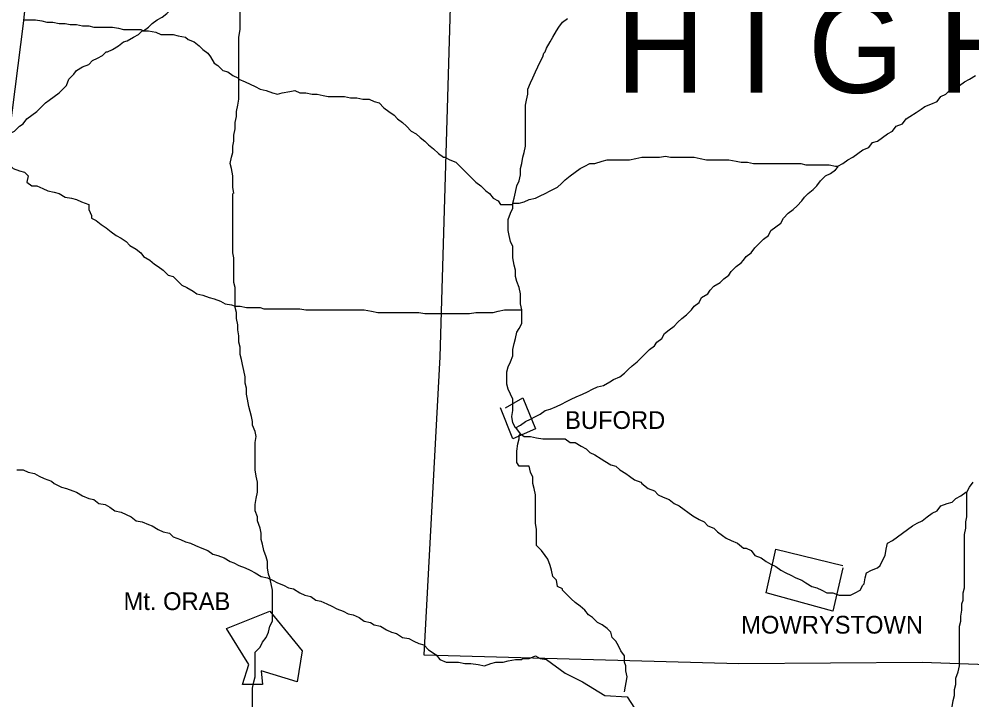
# Model space of a CAD drawing. Extents: x 0 to 34, y 0 to 22.
# Drawn here: x 2.531 to 3.578, y 17.75 to 18.498 of the extents above; entities that cross this region are included whole.
import ezdxf

# ---------------------------------------------------------------- set-up
doc = ezdxf.new("R2010")
doc.units = 0
doc.layers.add('Default', color=7, linetype='Continuous')
doc.layers.add('TR_Turning_Path1', color=7, linetype='Continuous')

msp = doc.modelspace()

# ---------------------------------------------------------------- linework, layer by layer
at = {"layer": 'Default'}
for points in [[(2.5636, 18.8615), (2.5554, 18.732), (2.5473, 18.6093), (2.535, 18.4934), (2.52, 18.3748), (2.5173, 18.3407), (2.5009, 18.2016), (2.4832, 18.0612), (2.4655, 17.914), (2.4109, 17.4668), (2.3877, 17.2759), (2.3646, 17.0891), (2.3209, 16.7073), (2.3168, 16.6787)], [(3.0135, 18.822), (2.9931, 18.1267), (2.9754, 17.7994), (3.3217, 17.7899), (3.5235, 17.7913), (3.6353, 17.7872), (3.6789, 17.7858)], [(2.6672, 18.4852), (2.6727, 18.4893), (2.6768, 18.4934), (2.6822, 18.4975), (2.6877, 18.5002), (2.6931, 18.5043), (2.6986, 18.5098), (2.7041, 18.5125), (2.7081, 18.5166), (2.7136, 18.5207), (2.719, 18.5234), (2.7245, 18.5275), (2.73, 18.5316), (2.7354, 18.5357), (2.7409, 18.5398), (2.745, 18.5439), (2.749, 18.5466), (2.7559, 18.548), (2.7627, 18.5493), (2.7695, 18.5507), (2.7722, 18.5507)], [(2.7722, 18.4321), (2.7722, 18.4402), (2.7722, 18.4457), (2.7722, 18.4539), (2.7722, 18.4593), (2.7722, 18.4662), (2.7722, 18.473), (2.7722, 18.4784), (2.7736, 18.4866), (2.7736, 18.4921), (2.7736, 18.4975), (2.7736, 18.5043), (2.7736, 18.5111), (2.7722, 18.5166), (2.7722, 18.5221), (2.7722, 18.5302), (2.7722, 18.5357), (2.7736, 18.5411), (2.7736, 18.548), (2.7722, 18.5507)], [(2.535, 18.4975), (2.5418, 18.4975), (2.5486, 18.4975), (2.5554, 18.4961), (2.5609, 18.4948), (2.5677, 18.4948), (2.5745, 18.4934), (2.5813, 18.4934), (2.5868, 18.4921), (2.5936, 18.4921), (2.6004, 18.4907), (2.6072, 18.4907), (2.6127, 18.4893), (2.6195, 18.4893), (2.6263, 18.4893), (2.6332, 18.4893), (2.64, 18.488), (2.6454, 18.4866), (2.6509, 18.4866), (2.6591, 18.4866), (2.6645, 18.4866), (2.6672, 18.4852)], [(3.109, 18.4621), (3.1104, 18.4662), (3.1144, 18.473), (3.1172, 18.4784), (3.1213, 18.4852), (3.124, 18.4893), (3.1281, 18.4948), (3.1335, 18.4989)], [(2.6277, 18.4621), (2.6332, 18.4648), (2.64, 18.4689), (2.6454, 18.473), (2.6495, 18.4743), (2.6563, 18.4784), (2.6618, 18.4811), (2.6659, 18.4852), (2.6672, 18.4852)], [(2.6672, 18.4852), (2.6727, 18.4852), (2.6809, 18.4839), (2.6863, 18.4811), (2.6918, 18.4811), (2.7, 18.4811), (2.7054, 18.4798), (2.7136, 18.4784), (2.7163, 18.4757), (2.7231, 18.473), (2.7286, 18.4689), (2.7327, 18.4648), (2.7381, 18.4607), (2.7409, 18.4566), (2.745, 18.4498), (2.749, 18.4471), (2.7545, 18.4416), (2.76, 18.4402), (2.7654, 18.4362), (2.7709, 18.4334), (2.7722, 18.4321)], [(2.52, 18.3721), (2.5254, 18.3748), (2.5309, 18.3803), (2.535, 18.383), (2.5391, 18.3884), (2.5445, 18.3925), (2.55, 18.3966), (2.5541, 18.4007), (2.5595, 18.4062), (2.5636, 18.4089), (2.5691, 18.413), (2.5745, 18.4171), (2.5786, 18.4212), (2.5827, 18.4252), (2.5854, 18.4321), (2.5909, 18.4375), (2.5936, 18.4416), (2.6004, 18.4457), (2.6072, 18.4484), (2.6113, 18.4525), (2.6168, 18.4552), (2.6222, 18.458), (2.6263, 18.4621), (2.6277, 18.4621)], [(3.0735, 18.2957), (3.0749, 18.3012), (3.0763, 18.308), (3.0776, 18.3148), (3.0804, 18.3203), (3.0817, 18.3271), (3.0817, 18.3339), (3.0831, 18.3394), (3.0844, 18.3462), (3.0858, 18.3516), (3.0872, 18.3584), (3.0872, 18.3639), (3.0872, 18.3707), (3.0872, 18.3775), (3.0872, 18.383), (3.0872, 18.3898), (3.0872, 18.3966), (3.0872, 18.4034), (3.0885, 18.4089), (3.0899, 18.4157), (3.0899, 18.4212), (3.0926, 18.428), (3.0954, 18.4334), (3.0981, 18.4402), (3.1008, 18.4457), (3.1035, 18.4512), (3.1063, 18.4566), (3.1076, 18.4607), (3.109, 18.4621)], [(2.7668, 18.3066), (2.7654, 18.3134), (2.7654, 18.3203), (2.7654, 18.3257), (2.764, 18.3339), (2.7627, 18.3394), (2.764, 18.3462), (2.7654, 18.3516), (2.7654, 18.3584), (2.7668, 18.3639), (2.7668, 18.3707), (2.7681, 18.3775), (2.7681, 18.3843), (2.7695, 18.3912), (2.7695, 18.3966), (2.7709, 18.4034), (2.7722, 18.4103), (2.7722, 18.4157), (2.7722, 18.4225), (2.7722, 18.4293), (2.7722, 18.4321)], [(2.7722, 18.4321), (2.779, 18.4293), (2.7845, 18.4266), (2.7899, 18.4239), (2.7954, 18.4212), (2.8022, 18.4198), (2.809, 18.4171), (2.8145, 18.4157), (2.8199, 18.4171), (2.8281, 18.4184), (2.8336, 18.4198), (2.839, 18.4171), (2.8458, 18.4171), (2.8527, 18.4157), (2.8581, 18.4157), (2.8649, 18.4143), (2.8704, 18.413), (2.8786, 18.413), (2.8827, 18.413), (2.8827, 18.413)], [(3.4308, 18.3366), (3.4362, 18.3394), (3.4417, 18.3434), (3.4471, 18.3462), (3.4526, 18.3503), (3.458, 18.3544), (3.4648, 18.3571), (3.4689, 18.3625), (3.4744, 18.3639), (3.4798, 18.368), (3.4853, 18.3721), (3.4907, 18.3748), (3.4948, 18.3803), (3.5017, 18.383), (3.5057, 18.3884), (3.5098, 18.3912), (3.5167, 18.3953), (3.5221, 18.3993), (3.5262, 18.4021), (3.533, 18.4048), (3.5398, 18.4075), (3.5439, 18.413), (3.5494, 18.4157), (3.5535, 18.4198), (3.5589, 18.4225), (3.5644, 18.4252), (3.5698, 18.4293), (3.5753, 18.4321), (3.5821, 18.4362)], [(2.8827, 18.413), (2.8881, 18.413), (2.8949, 18.4116), (2.9017, 18.4116), (2.9086, 18.4103), (2.9154, 18.4103), (2.9208, 18.4075), (2.9263, 18.4062), (2.9317, 18.4007), (2.9372, 18.3966), (2.9427, 18.3925), (2.9467, 18.3884), (2.9522, 18.3843), (2.9563, 18.3803), (2.9617, 18.3748), (2.9672, 18.3721), (2.9713, 18.368), (2.9767, 18.3639), (2.9808, 18.3598), (2.9863, 18.3557), (2.9917, 18.3503), (2.9972, 18.3462), (2.9986, 18.3462)], [(2.5173, 18.3475), (2.52, 18.3434), (2.52, 18.338), (2.5241, 18.3339), (2.5309, 18.3312), (2.5364, 18.3298), (2.5404, 18.3257), (2.5391, 18.3189), (2.5445, 18.3148), (2.55, 18.3148), (2.5568, 18.3121), (2.5623, 18.3094), (2.5691, 18.308), (2.5745, 18.3066), (2.5813, 18.3025), (2.5882, 18.3012), (2.5936, 18.2998), (2.5991, 18.2971), (2.6072, 18.2944), (2.6072, 18.2889), (2.61, 18.2821), (2.61, 18.2821), (2.61, 18.2794)], [(2.9986, 18.3462), (3.004, 18.3434), (3.0108, 18.3407), (3.0135, 18.338), (3.019, 18.3325), (3.0245, 18.3271), (3.0285, 18.323), (3.0326, 18.3189), (3.0381, 18.3148), (3.0435, 18.3094), (3.0476, 18.3066), (3.0517, 18.3012), (3.0572, 18.2985), (3.0599, 18.2944), (3.0667, 18.2944), (3.0735, 18.2944), (3.0735, 18.2957)], [(3.0735, 18.2957), (3.0804, 18.2957), (3.0858, 18.2971), (3.0913, 18.2998), (3.0981, 18.3012), (3.1035, 18.3039), (3.109, 18.3066), (3.1144, 18.3094), (3.1226, 18.3134), (3.1267, 18.3175), (3.1308, 18.3216), (3.1363, 18.3257), (3.1417, 18.3298), (3.1472, 18.3339), (3.1526, 18.3366), (3.1581, 18.3394), (3.1635, 18.3394), (3.1717, 18.3421), (3.1772, 18.3434), (3.1826, 18.3434), (3.1894, 18.3434), (3.1962, 18.3434), (3.2017, 18.3434), (3.2085, 18.3448), (3.2153, 18.3462), (3.2208, 18.3462), (3.2276, 18.3462), (3.229, 18.3462)], [(3.229, 18.3462), (3.2344, 18.3462), (3.2412, 18.3475), (3.2467, 18.3462), (3.2535, 18.3462), (3.2603, 18.3462), (3.2658, 18.3462), (3.2726, 18.3462), (3.2794, 18.3448), (3.2862, 18.3434), (3.293, 18.3434), (3.2985, 18.3434), (3.3053, 18.3434), (3.3108, 18.3434), (3.319, 18.3421), (3.3244, 18.3407), (3.3312, 18.3407), (3.338, 18.3394), (3.3449, 18.3394), (3.3517, 18.3394), (3.3571, 18.3394), (3.3626, 18.3394), (3.3708, 18.3394), (3.3762, 18.3394), (3.383, 18.3394), (3.3899, 18.3394), (3.3953, 18.338), (3.4035, 18.338), (3.4089, 18.338), (3.4171, 18.338), (3.4212, 18.338), (3.428, 18.3366), (3.4308, 18.3366)], [(3.3271, 18.233), (3.3299, 18.2371), (3.3353, 18.2412), (3.3394, 18.2466), (3.3449, 18.2521), (3.3489, 18.2562), (3.3544, 18.2603), (3.3571, 18.2657), (3.3626, 18.2698), (3.368, 18.2739), (3.3708, 18.2794), (3.3762, 18.2848), (3.3817, 18.2889), (3.3858, 18.293), (3.3912, 18.2985), (3.3939, 18.3025), (3.398, 18.3066), (3.4035, 18.3107), (3.4076, 18.3148), (3.4117, 18.3203), (3.4171, 18.3257), (3.4226, 18.3284), (3.428, 18.3325), (3.4308, 18.3353), (3.4308, 18.3366)], [(2.7681, 18.1826), (2.7681, 18.1894), (2.7681, 18.1962), (2.7681, 18.203), (2.7668, 18.2085), (2.7668, 18.2153), (2.7668, 18.2221), (2.7668, 18.2276), (2.7668, 18.2357), (2.7654, 18.2412), (2.7654, 18.2466), (2.7654, 18.2535), (2.7654, 18.2603), (2.7654, 18.2671), (2.7654, 18.2725), (2.7654, 18.2794), (2.7654, 18.2862), (2.7654, 18.293), (2.7654, 18.2998), (2.7654, 18.3066), (2.7654, 18.3066)], [(3.0831, 18.1785), (3.0817, 18.1853), (3.0817, 18.1921), (3.0817, 18.1962), (3.0804, 18.203), (3.0776, 18.2098), (3.0763, 18.2153), (3.0763, 18.2221), (3.0749, 18.2276), (3.0735, 18.2357), (3.0735, 18.2412), (3.0735, 18.248), (3.0708, 18.2535), (3.0694, 18.2603), (3.0681, 18.2657), (3.0681, 18.2725), (3.0681, 18.278), (3.0708, 18.2848), (3.0735, 18.2903), (3.0735, 18.2957)], [(2.61, 18.2794), (2.6154, 18.2766), (2.6209, 18.2725), (2.6263, 18.2685), (2.6318, 18.2644), (2.6372, 18.2603), (2.6427, 18.2575), (2.6482, 18.2535), (2.6522, 18.2494), (2.6591, 18.2453), (2.6645, 18.2412), (2.6672, 18.2371), (2.6741, 18.233), (2.6795, 18.2289), (2.6836, 18.2262), (2.6891, 18.2221), (2.6945, 18.2166), (2.7, 18.2153), (2.7054, 18.2098), (2.7095, 18.2057), (2.715, 18.203), (2.7218, 18.1989), (2.7259, 18.1962), (2.7327, 18.1948), (2.7395, 18.1921), (2.745, 18.1907), (2.7518, 18.188), (2.7572, 18.1853), (2.764, 18.1839), (2.7681, 18.1826), (2.7681, 18.1826)], [(3.2044, 18.1171), (3.2099, 18.1212), (3.214, 18.1253), (3.2181, 18.1294), (3.2235, 18.1348), (3.229, 18.1389), (3.2317, 18.143), (3.2371, 18.1471), (3.2399, 18.1526), (3.2453, 18.1567), (3.2508, 18.1607), (3.2549, 18.1648), (3.259, 18.1689), (3.2644, 18.173), (3.2699, 18.1785), (3.2726, 18.1826), (3.2781, 18.1867), (3.2808, 18.1921), (3.2876, 18.1962), (3.2903, 18.2003), (3.2944, 18.2044), (3.3012, 18.2085), (3.3053, 18.2126), (3.3108, 18.2166), (3.3135, 18.2207), (3.319, 18.2262), (3.3244, 18.2303), (3.3271, 18.233), (3.3271, 18.233)], [(2.7681, 18.1826), (2.7736, 18.1826), (2.7804, 18.1812), (2.7872, 18.1812), (2.7954, 18.1812), (2.7995, 18.1798), (2.8063, 18.1798), (2.8145, 18.1798), (2.8199, 18.1798), (2.8281, 18.1798), (2.8336, 18.1798), (2.839, 18.1798), (2.8458, 18.1785), (2.8527, 18.1785), (2.8595, 18.1785), (2.8649, 18.1785), (2.8718, 18.1785), (2.8786, 18.1785), (2.8854, 18.1785), (2.8908, 18.1785), (2.8977, 18.1785), (2.9045, 18.1785), (2.9099, 18.1785), (2.9181, 18.1771), (2.9249, 18.1757), (2.9304, 18.1757), (2.9372, 18.1757), (2.944, 18.1757), (2.9508, 18.1757), (2.9563, 18.1757), (2.9631, 18.1757), (2.9699, 18.1757), (2.9767, 18.1744), (2.9836, 18.1744), (2.989, 18.1744), (2.9931, 18.1744), (2.9931, 18.1744)], [(2.7859, 18.0612), (2.7845, 18.0667), (2.7831, 18.0721), (2.7818, 18.0803), (2.7804, 18.0858), (2.7804, 18.0926), (2.779, 18.098), (2.779, 18.1048), (2.7777, 18.1117), (2.7763, 18.1185), (2.7749, 18.1239), (2.7736, 18.1294), (2.7736, 18.1376), (2.7722, 18.143), (2.7722, 18.1498), (2.7709, 18.1567), (2.7709, 18.1621), (2.7695, 18.1689), (2.7695, 18.1757), (2.7681, 18.1812), (2.7681, 18.1826)], [(2.9931, 18.1744), (2.9999, 18.1744), (3.0054, 18.1744), (3.0122, 18.1744), (3.019, 18.1744), (3.0258, 18.1744), (3.0326, 18.1757), (3.0381, 18.1757), (3.0435, 18.1757), (3.0517, 18.1757), (3.0572, 18.1771), (3.064, 18.1785), (3.0708, 18.1785), (3.0776, 18.1785), (3.0831, 18.1785)], [(3.0763, 18.0489), (3.0735, 18.0544), (3.0722, 18.0612), (3.0735, 18.068), (3.0735, 18.0735), (3.0735, 18.0803), (3.0708, 18.0858), (3.0681, 18.0912), (3.0667, 18.0967), (3.0667, 18.1048), (3.0667, 18.1103), (3.0681, 18.1158), (3.0708, 18.1212), (3.0735, 18.128), (3.0735, 18.1348), (3.0749, 18.1417), (3.0763, 18.1471), (3.0776, 18.1539), (3.0804, 18.158), (3.0831, 18.1635), (3.0831, 18.1703), (3.0831, 18.1757), (3.0831, 18.1785)], [(3.0763, 18.0489), (3.0817, 18.0517), (3.0872, 18.0558), (3.0926, 18.0585), (3.0981, 18.0612), (3.1035, 18.0639), (3.109, 18.068), (3.1144, 18.0694), (3.1213, 18.0721), (3.1267, 18.0749), (3.1322, 18.0776), (3.1376, 18.0803), (3.1431, 18.083), (3.1499, 18.0858), (3.1553, 18.0885), (3.1608, 18.0912), (3.1663, 18.0939), (3.1731, 18.0953), (3.1799, 18.0994), (3.184, 18.1021), (3.1908, 18.1048), (3.1962, 18.1089), (3.2003, 18.113), (3.2044, 18.1171), (3.2044, 18.1171)], [(3.0654, 18.0708), (3.0844, 18.0817), (3.0981, 18.0476), (3.0735, 18.0367), (3.0599, 18.0708)], [(2.7899, 18.0067), (2.7899, 18.0135), (2.7899, 18.0203), (2.7899, 18.0258), (2.7899, 18.0326), (2.7913, 18.0394), (2.7899, 18.0449), (2.7872, 18.0517), (2.7872, 18.0558), (2.7859, 18.0612)], [(3.0817, 18.0421), (3.0776, 18.0476), (3.0763, 18.0489)], [(3.0994, 17.9303), (3.0994, 17.9371), (3.0981, 17.944), (3.0981, 17.9508), (3.0981, 17.9576), (3.0981, 17.963), (3.0981, 17.9699), (3.0981, 17.9753), (3.0967, 17.9821), (3.0954, 17.9876), (3.0954, 17.9944), (3.0926, 17.9999), (3.0913, 18.0067), (3.0858, 18.0067), (3.0804, 18.0067), (3.0776, 18.0108), (3.0776, 18.0176), (3.0776, 18.023), (3.079, 18.0312), (3.0804, 18.0367), (3.0804, 18.0408), (3.0817, 18.0421)], [(3.0817, 18.0421), (3.0858, 18.0394), (3.0926, 18.0394), (3.0994, 18.038), (3.1063, 18.0367), (3.1117, 18.0367), (3.1172, 18.0367), (3.124, 18.0367), (3.1308, 18.0367), (3.1363, 18.0326), (3.1417, 18.0326), (3.1485, 18.0285), (3.154, 18.0258), (3.1581, 18.0217), (3.1635, 18.019), (3.1703, 18.0149), (3.1744, 18.0121), (3.1812, 18.008), (3.1867, 18.0067), (3.1908, 18.0026), (3.1976, 17.9985), (3.2017, 17.9958), (3.2072, 17.9917), (3.214, 17.989), (3.2153, 17.9876), (3.2153, 17.9876)], [(2.5282, 18.0026), (2.535, 18.0026), (2.5404, 17.9999), (2.5473, 17.9985), (2.5527, 17.9958), (2.5582, 17.993), (2.5663, 17.9903), (2.5691, 17.9876), (2.5773, 17.9835), (2.5827, 17.9821), (2.5895, 17.9794), (2.5936, 17.978), (2.6004, 17.974), (2.6072, 17.9712), (2.6127, 17.9699), (2.6182, 17.9658), (2.625, 17.9644), (2.6304, 17.9617), (2.6359, 17.9576), (2.6427, 17.9562), (2.6482, 17.9535), (2.6536, 17.9508), (2.6591, 17.9467), (2.6659, 17.9453), (2.6727, 17.9426), (2.6768, 17.9412), (2.6836, 17.9371), (2.6891, 17.9344), (2.6959, 17.9331), (2.7, 17.929), (2.7081, 17.9262), (2.7136, 17.9235), (2.719, 17.9221), (2.7245, 17.9194), (2.7313, 17.9167), (2.7381, 17.914), (2.7436, 17.9099), (2.749, 17.9085), (2.7559, 17.9058), (2.7627, 17.9017), (2.7668, 17.9003), (2.7722, 17.8976), (2.779, 17.8949), (2.7845, 17.8922), (2.7899, 17.8894), (2.7968, 17.8853), (2.8036, 17.884), (2.809, 17.8812), (2.8145, 17.8785), (2.8213, 17.8758), (2.8268, 17.8731), (2.8322, 17.8717), (2.839, 17.8676), (2.8445, 17.8649), (2.8513, 17.8635), (2.8568, 17.8594), (2.8622, 17.8581), (2.869, 17.8553), (2.8745, 17.8526), (2.8799, 17.8499), (2.8868, 17.8472), (2.8922, 17.8444), (2.8977, 17.8431), (2.9045, 17.8403), (2.9099, 17.8363), (2.9167, 17.8349), (2.9208, 17.8322), (2.9277, 17.8308), (2.9345, 17.8267), (2.9399, 17.824), (2.9454, 17.8226), (2.9522, 17.8185), (2.959, 17.8172), (2.9645, 17.8144), (2.9699, 17.8117), (2.9754, 17.8103)], [(2.8063, 17.8308), (2.809, 17.8363), (2.809, 17.8431), (2.809, 17.8512), (2.809, 17.8567), (2.809, 17.8635), (2.809, 17.8703), (2.8077, 17.8772), (2.8063, 17.884), (2.8049, 17.8881), (2.8036, 17.8949), (2.8036, 17.9017), (2.8022, 17.9071), (2.7995, 17.914), (2.7981, 17.9208), (2.7968, 17.9262), (2.7968, 17.9331), (2.7954, 17.9385), (2.7927, 17.9467), (2.7927, 17.9508), (2.7899, 17.9576), (2.7899, 17.9644), (2.7913, 17.9712), (2.7927, 17.978), (2.7927, 17.9821), (2.7927, 17.989), (2.7913, 17.9958), (2.7899, 18.0026), (2.7899, 18.0067), (2.7899, 18.0067)], [(3.2153, 17.9876), (3.2222, 17.9821), (3.229, 17.9794), (3.2331, 17.9753), (3.2385, 17.9726), (3.2453, 17.9699), (3.2508, 17.9658), (3.2562, 17.963), (3.2617, 17.959), (3.2658, 17.9562), (3.2712, 17.9521), (3.2781, 17.9481), (3.2835, 17.9453), (3.2876, 17.9412), (3.2944, 17.9385), (3.2985, 17.9344), (3.304, 17.9303), (3.308, 17.9276), (3.3135, 17.9249), (3.3203, 17.9221), (3.3271, 17.9167), (3.3299, 17.9167)], [(3.5726, 17.978), (3.5753, 17.9835), (3.5794, 17.989)], [(3.4594, 17.8772), (3.4608, 17.884), (3.4621, 17.8894), (3.4676, 17.8922), (3.4744, 17.8949), (3.4771, 17.8976), (3.4798, 17.9031), (3.4826, 17.9085), (3.4839, 17.9153), (3.4853, 17.9221), (3.4907, 17.9249), (3.4962, 17.929), (3.5017, 17.9331), (3.5071, 17.9371), (3.5126, 17.9412), (3.518, 17.944), (3.5235, 17.9467), (3.5289, 17.9508), (3.5344, 17.9549), (3.5398, 17.9576), (3.5439, 17.963), (3.5507, 17.9658), (3.5562, 17.9671), (3.5603, 17.9712), (3.5657, 17.974), (3.5712, 17.978), (3.5726, 17.978)], [(3.5644, 17.7913), (3.5644, 17.7981), (3.5644, 17.8035), (3.5644, 17.8103), (3.5644, 17.8172), (3.5644, 17.824), (3.5644, 17.8308), (3.5657, 17.8363), (3.5657, 17.8417), (3.5671, 17.8485), (3.5671, 17.8553), (3.5685, 17.8594), (3.5685, 17.8676), (3.5698, 17.8731), (3.5698, 17.8812), (3.5698, 17.8853), (3.5698, 17.8922), (3.5698, 17.899), (3.5698, 17.9058), (3.5698, 17.9112), (3.5698, 17.9194), (3.5698, 17.9249), (3.5698, 17.9317), (3.5712, 17.9385), (3.5712, 17.9453), (3.5726, 17.9508), (3.5726, 17.9576), (3.5726, 17.9644), (3.5726, 17.9712), (3.5726, 17.978), (3.5726, 17.978)], [(3.1281, 17.8717), (3.1226, 17.8744), (3.1213, 17.8812), (3.1172, 17.8853), (3.1158, 17.8922), (3.1144, 17.8976), (3.1117, 17.9044), (3.109, 17.9085), (3.1049, 17.914), (3.0994, 17.9194), (3.0994, 17.9249), (3.0994, 17.929), (3.0994, 17.9303)], [(3.1281, 17.8717), (3.1226, 17.8744), (3.1213, 17.8812), (3.1172, 17.8853), (3.1158, 17.8922), (3.1144, 17.8976), (3.1117, 17.9044), (3.109, 17.9085), (3.1049, 17.914), (3.0994, 17.9194), (3.0994, 17.9249), (3.0994, 17.929), (3.0994, 17.9303)], [(3.3299, 17.9167), (3.3353, 17.914), (3.3394, 17.9085), (3.3462, 17.9058), (3.3517, 17.9017), (3.3571, 17.899), (3.3626, 17.8962), (3.368, 17.8922), (3.3735, 17.8894), (3.3789, 17.8867), (3.3844, 17.884), (3.3912, 17.8812), (3.3953, 17.8785), (3.4021, 17.8744), (3.4076, 17.8731), (3.413, 17.8703), (3.4185, 17.8676), (3.4253, 17.8676), (3.4321, 17.8649), (3.4376, 17.8649), (3.4444, 17.8649), (3.4498, 17.8676), (3.4553, 17.8703), (3.458, 17.8758), (3.458, 17.8758), (3.4594, 17.8772)], [(3.4362, 17.8949), (3.4253, 17.8472), (3.3517, 17.8676), (3.3626, 17.9153), (3.4362, 17.8976)], [(3.1962, 17.7913), (3.1962, 17.7981), (3.1922, 17.8035), (3.1894, 17.809), (3.1867, 17.8144), (3.1826, 17.8185), (3.1812, 17.824), (3.1772, 17.8281), (3.1717, 17.8322), (3.1663, 17.8349), (3.1608, 17.8403), (3.1567, 17.8431), (3.1526, 17.8485), (3.1472, 17.8526), (3.1417, 17.8567), (3.1376, 17.8608), (3.1335, 17.8649), (3.1281, 17.8703), (3.1281, 17.8717)], [(3.1962, 17.7913), (3.1962, 17.7981), (3.1922, 17.8035), (3.1894, 17.809), (3.1867, 17.8144), (3.1826, 17.8185), (3.1812, 17.824), (3.1772, 17.8281), (3.1717, 17.8322), (3.1663, 17.8349), (3.1608, 17.8403), (3.1567, 17.8431), (3.1526, 17.8485), (3.1472, 17.8526), (3.1417, 17.8567), (3.1376, 17.8608), (3.1335, 17.8649), (3.1281, 17.8703), (3.1281, 17.8717)], [(2.8063, 17.8472), (2.8418, 17.8035), (2.8363, 17.7694), (2.7968, 17.7817), (2.7981, 17.7667), (2.7763, 17.7667), (2.7831, 17.7885), (2.7586, 17.8281), (2.8063, 17.8472)], [(2.7968, 17.6999), (2.7968, 17.7054), (2.7954, 17.7122), (2.7927, 17.7176), (2.7899, 17.7245), (2.7899, 17.7299), (2.7872, 17.7367), (2.7872, 17.7435), (2.7872, 17.7504), (2.7872, 17.7572), (2.7872, 17.7626), (2.7886, 17.7694), (2.7899, 17.7749), (2.7899, 17.7817), (2.7899, 17.7899), (2.7899, 17.7953), (2.7899, 17.8022), (2.7954, 17.8076), (2.7981, 17.8131), (2.8022, 17.8185), (2.8049, 17.824), (2.8063, 17.8308), (2.8063, 17.8308)], [(2.9754, 17.8103), (2.9808, 17.8049), (2.989, 17.7994)], [(2.989, 17.7994), (2.9931, 17.794), (2.9999, 17.7913), (3.0081, 17.7913), (3.0135, 17.7913), (3.0204, 17.7899), (3.0272, 17.7899), (3.0354, 17.7885), (3.0422, 17.7872), (3.049, 17.7899), (3.0545, 17.7913), (3.0626, 17.7913), (3.0681, 17.7926), (3.0763, 17.794), (3.0831, 17.794), (3.0844, 17.7953)], [(3.0844, 17.7953), (3.0913, 17.7953), (3.0981, 17.7981), (3.1035, 17.7953), (3.1104, 17.794)], [(3.1104, 17.794), (3.1308, 17.779), (3.1499, 17.7694), (3.1744, 17.7544), (3.199, 17.7531), (3.2072, 17.7408), (3.2467, 17.7176), (3.289, 17.6808), (3.3244, 17.6522), (3.3762, 17.6263), (3.3994, 17.6099), (3.4294, 17.5731), (3.4717, 17.5608), (3.4867, 17.554)], [(3.1962, 17.7585), (3.199, 17.7749), (3.1976, 17.7817), (3.1976, 17.7872), (3.1962, 17.7913)], [(3.5289, 17.6576), (3.5289, 17.6631), (3.5316, 17.6699), (3.533, 17.6754), (3.5344, 17.6808), (3.5357, 17.6876), (3.5398, 17.6945), (3.5412, 17.6999), (3.5453, 17.7054), (3.548, 17.7122), (3.5494, 17.7176), (3.5507, 17.7231), (3.5521, 17.7299), (3.5535, 17.7367), (3.5562, 17.7422), (3.5576, 17.749), (3.5589, 17.7544), (3.5589, 17.7613), (3.5603, 17.7667), (3.5603, 17.7735), (3.563, 17.7804), (3.5644, 17.7872), (3.5644, 17.7913)]]:
    msp.add_lwpolyline(points, dxfattribs=at)

# ---------------------------------------------------------------- texts
for s, p in [('BUFORD', (3.1308, 18.0476)), ('Mt. ORAB', (2.6454, 17.8485)), ('MOWRYSTOWN', (3.3244, 17.8226))]:
    msp.add_text(s, height=0.0195, dxfattribs=at).set_placement(p)
at = {"layer": 'TR_Turning_Path1'}
msp.add_text('H I G H L A N D', height=0.101489, dxfattribs=at).set_placement((3.1867, 18.4171))

doc.saveas('drawing.dxf')
